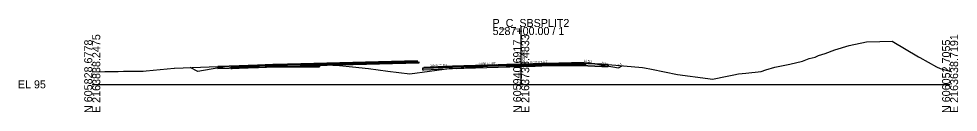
# Model space of a CAD drawing. Extents: x -26 to 1303, y -10 to 12033.
# Drawn here: x -25.7 to 302.8, y 3990.3 to 4022.8 of the extents above; entities that cross this region are included whole.
import ezdxf

# ---------------------------------------------------------------- set-up
doc = ezdxf.new("R2010")
doc.units = 0
for name, color, linetype in [('RD_GPK_XS_Cell', 7, 'Continuous'), ('RD_XS_Base', 7, 'Continuous'), ('RD_XS_ExGround', 7, 'Continuous'), ('RD_XS_ExPaveRet', 7, 'Continuous'), ('RD_XS_Greenside', 7, 'Continuous'), ('RD_XS_Pave', 7, 'Continuous'), ('RD_XS_PaveOvlay_CP', 7, 'Continuous'), ('RD_XS_TieSlope', 7, 'Continuous'), ('RD_XS_TX_Elev_EX', 7, 'Continuous'), ('RD_XS_TX_Elev_PR', 7, 'Continuous'), ('RD_XS_TX_ShdSlope', 7, 'Continuous'), ('RD_XS_TX_Slope', 7, 'Continuous')]:
    doc.layers.add(name, color=color, linetype=linetype)

msp = doc.modelspace()

# ---------------------------------------------------------------- linework, layer by layer
at = {"layer": 'RD_GPK_XS_Cell'}
for p, q in [((150, 4000), (150, 4020)), ((0, 4000), (150, 4000)), ((150, 4000), (300, 4000))]:
    msp.add_line(p, q, dxfattribs=at)
at = {"layer": 'RD_XS_Base'}
for p, q in [((48.51, 4006.03), (48.41, 4006.02)), ((48.41, 4006.02), (48.41, 4005.62)), ((48.41, 4005.62), (48.41, 4005.52)), ((48.41, 4005.52), (48.51, 4005.53)), ((48.91, 4006.04), (48.51, 4006.03)), ((48.51, 4005.53), (48.91, 4005.54)), ((51.32, 4006.14), (48.91, 4006.04)), ((48.91, 4005.54), (51.32, 4005.64)), ((60.91, 4006.52), (51.32, 4006.14)), ((51.32, 4005.64), (60.91, 4006.02)), ((63.58, 4006.59), (60.91, 4006.52)), ((60.91, 4006.02), (63.58, 4006.09)), ((72.91, 4006.84), (63.58, 4006.59)), ((63.58, 4006.09), (72.91, 4006.34)), ((72.91, 4006.84), (114.23, 4007.91)), ((114.23, 4007.41), (72.91, 4006.34)), ((72.91, 4006.34), (72.91, 4006.99)), ((72.91, 4006.99), (72.91, 4006.99)), ((72.91, 4006.99), (72.91, 4006.99)), ((72.91, 4006.99), (72.91, 4006.84)), ((72.91, 4006.84), (72.91, 4006.84)), ((72.91, 4006.34), (72.91, 4006.84)), ((72.91, 4006.84), (72.91, 4006.84)), ((72.91, 4006.84), (72.91, 4006.84)), ((72.91, 4006.34), (72.91, 4006.34)), ((96.91, 4007.46), (96.91, 4007.46)), ((96.91, 4007.46), (96.91, 4007.46)), ((96.91, 4006.96), (96.91, 4006.96)), ((96.91, 4006.96), (96.91, 4006.96)), ((113.73, 4007.9), (113.73, 4007.9)), ((114.23, 4007.91), (114.23, 4007.41)), ((114.23, 4007.88), (114.23, 4007.88)), ((116, 4005.61), (115.5, 4005.59)), ((115.5, 4005.59), (115.5, 4005.59)), ((115.5, 4005.59), (115.5, 4005.09)), ((115.5, 4005.09), (116, 4005.11)), ((126, 4006.01), (116, 4005.61)), ((116, 4005.61), (116, 4005.61)), ((116, 4005.11), (126, 4005.51)), ((116, 4005.11), (116, 4005.11)), ((150, 4006.68), (126, 4006.01)), ((126, 4005.51), (150, 4006.18)), ((126, 4006.01), (126, 4006.01)), ((126, 4005.51), (126, 4005.51)), ((150, 4006.68), (172, 4007.29)), ((150, 4006.18), (150, 4006.84)), ((150, 4006.84), (150, 4006.84)), ((150, 4006.84), (150, 4006.84)), ((150, 4006.84), (150, 4006.68)), ((172.5, 4006.81), (150, 4006.18)), ((150, 4006.68), (150, 4006.68)), ((150, 4006.18), (150, 4006.68)), ((150, 4006.68), (150, 4006.68)), ((150, 4006.68), (150, 4006.68)), ((150, 4006.18), (150, 4006.18)), ((162, 4007.01), (162, 4007.01)), ((162, 4007.01), (162, 4007.01)), ((162, 4006.51), (162, 4006.51)), ((162, 4006.51), (162, 4006.51)), ((172, 4007.29), (172, 4007.29)), ((172.5, 4007.31), (172.5, 4006.81)), ((172.5, 4007.27), (172.5, 4007.27))]:
    msp.add_line(p, q, dxfattribs=at)
at = {"layer": 'RD_XS_ExGround'}
msp.add_lwpolyline([(0, 4004.37), (4.41, 4004.44), (9.06, 4004.53), (10.96, 4004.56), (17.84, 4004.65), (18.81, 4004.66), (28.68, 4005.66), (28.76, 4005.67), (28.78, 4005.67), (43.88, 4006.26), (58.56, 4006.69), (60.53, 4006.75), (62.32, 4006.84), (63.44, 4006.89), (64.65, 4006.89), (79.47, 4006.87), (86.45, 4006.56), (91.02, 4006.15), (96.66, 4005.54), (103.41, 4004.64), (111.03, 4003.62), (124.76, 4005.53), (125.53, 4005.62), (125.59, 4005.62), (127.35, 4005.48), (135.26, 4006.1), (139.62, 4006.41), (144.95, 4006.87), (147.45, 4006.97), (154.9, 4007.13), (157.23, 4007.25), (160.3, 4007.31), (160.68, 4007.27), (163.58, 4007.31), (167.65, 4007.35), (170.9, 4007.34), (178.24, 4007.01), (180.42, 4006.93), (192.44, 4005.82), (193.11, 4005.76), (195.59, 4005.27), (204.64, 4003.49), (215.27, 4002), (216.9, 4001.76), (222.03, 4002.82), (224.37, 4003.3), (225.95, 4003.65), (228.58, 4003.89), (233.88, 4004.46), (235.59, 4005.08), (238.76, 4005.99), (243.96, 4007.02), (248.39, 4008.14), (250.7, 4008.98), (252.84, 4009.51), (254.02, 4010.02), (256.29, 4010.79), (259.74, 4012.01), (264.65, 4013.5), (270.81, 4014.82), (275.43, 4014.95), (279.74, 4015.1), (288.97, 4009.58), (289.16, 4009.47), (289.38, 4009.33), (295.21, 4006.07), (296.5, 4005.51), (298.12, 4005.02), (300, 4004.6)], dxfattribs=at)
at = {"layer": 'RD_XS_ExPaveRet'}
for points in [[(79.47, 4006.87), (79.47, 4006.87), (79.47, 4006.29), (79.47, 4006.12), (79.47, 4006.12), (79.47, 4006.12), (77.26, 4006.12), (64.65, 4006.14), (63.69, 4006.14), (63.44, 4006.14), (63.2, 4006.13), (62.84, 4006.11), (60.62, 4006.01), (60.48, 4006), (58.1, 4005.93), (57.74, 4005.92), (55.8, 4005.86), (43.88, 4005.51), (43.88, 4005.58), (43.88, 4006.26), (55.8, 4006.61), (57.74, 4006.67), (58.1, 4006.68), (60.48, 4006.75), (60.62, 4006.76), (62.84, 4006.86), (63.2, 4006.88), (63.44, 4006.89), (63.69, 4006.89), (64.65, 4006.89), (77.26, 4006.87), (79.47, 4006.87), (79.47, 4006.87)], [(79.47, 4006.87), (77.26, 4006.87), (64.65, 4006.89), (63.69, 4006.89), (63.44, 4006.89), (63.2, 4006.88), (62.84, 4006.86), (60.62, 4006.76), (60.48, 4006.75), (58.1, 4006.68), (57.74, 4006.67), (55.8, 4006.61), (43.88, 4006.26), (43.88, 4005.58), (43.88, 4005.51), (55.8, 4005.86), (57.74, 4005.92), (58.1, 4005.93), (60.48, 4006), (60.62, 4006.01), (62.84, 4006.11), (63.2, 4006.13), (63.44, 4006.14), (63.69, 4006.14), (64.65, 4006.14), (77.26, 4006.12), (79.47, 4006.12), (79.47, 4006.12), (79.47, 4006.29), (79.47, 4006.87)], [(79.47, 4006.87), (79.47, 4006.87)], [(180.42, 4006.93), (180.42, 4006.93), (180.42, 4006.18), (178.24, 4006.26), (178.24, 4006.26), (170.9, 4006.59), (170.9, 4006.59), (170.9, 4006.59), (167.65, 4006.6), (163.58, 4006.56), (163.58, 4006.56), (160.68, 4006.52), (160.68, 4006.52), (160.68, 4006.52), (160.3, 4006.56), (160.3, 4006.56), (157.23, 4006.5), (154.9, 4006.38), (154.9, 4006.38), (147.45, 4006.22), (147.45, 4006.22), (144.95, 4006.12), (144.95, 4006.12), (144.95, 4006.87), (144.95, 4006.87), (144.95, 4006.87), (147.45, 4006.97), (147.45, 4006.97), (154.9, 4007.13), (154.9, 4007.13), (157.23, 4007.25), (160.3, 4007.31), (160.3, 4007.31), (160.68, 4007.27), (160.68, 4007.27), (160.68, 4007.27), (163.58, 4007.31), (163.58, 4007.31), (167.65, 4007.35), (170.9, 4007.34), (170.9, 4007.34), (170.9, 4007.34), (178.24, 4007.01), (178.24, 4007.01), (180.42, 4006.93)], [(178.24, 4007.01), (170.9, 4007.34), (167.65, 4007.35), (163.58, 4007.31), (160.68, 4007.27), (160.3, 4007.31), (157.23, 4007.25), (154.9, 4007.13), (147.45, 4006.97), (144.95, 4006.87), (144.95, 4006.87), (144.95, 4006.12), (144.95, 4006.12), (147.45, 4006.22), (154.9, 4006.38), (157.23, 4006.5), (160.3, 4006.56), (160.68, 4006.52), (163.58, 4006.56), (167.65, 4006.6), (170.9, 4006.59), (178.24, 4006.26), (180.42, 4006.18), (180.42, 4006.93), (178.24, 4007.01)]]:
    msp.add_lwpolyline(points, dxfattribs=at)
at = {"layer": 'RD_XS_Greenside'}
for p, q in [((36.91, 4004.54), (34.23, 4005.88)), ((46.91, 4006.2), (36.91, 4004.54)), ((174, 4007.45), (184, 4005.79)), ((184, 4005.79), (185.37, 4006.47))]:
    msp.add_line(p, q, dxfattribs=at)
at = {"layer": 'RD_XS_Pave'}
for p, q in [((113.73, 4008.21), (72.91, 4007.15)), ((113.73, 4008.06), (113.73, 4008.21)), ((113.73, 4008.21), (113.73, 4008.21)), ((51.32, 4006.46), (48.91, 4006.36)), ((48.91, 4006.36), (48.91, 4006.23)), ((48.91, 4006.2), (51.32, 4006.3)), ((51.32, 4006.3), (48.91, 4006.2)), ((48.91, 4006.23), (48.91, 4006.2)), ((48.91, 4006.2), (48.91, 4006.08)), ((48.91, 4006.04), (51.32, 4006.14)), ((48.91, 4006.08), (48.91, 4006.04)), ((60.91, 4006.84), (51.32, 4006.46)), ((51.32, 4006.3), (60.91, 4006.68)), ((60.91, 4006.68), (51.32, 4006.3)), ((51.32, 4006.14), (60.91, 4006.52)), ((63.58, 4006.91), (60.91, 4006.84)), ((60.91, 4006.68), (63.58, 4006.75)), ((63.58, 4006.75), (60.91, 4006.68)), ((60.91, 4006.52), (63.58, 4006.59)), ((72.91, 4007.15), (63.58, 4006.91)), ((63.58, 4006.75), (72.91, 4006.99)), ((72.91, 4006.99), (63.58, 4006.75)), ((63.58, 4006.59), (72.91, 4006.84)), ((113.73, 4008.06), (72.91, 4006.99)), ((72.91, 4006.99), (113.73, 4008.06)), ((72.91, 4006.84), (113.73, 4007.9)), ((72.91, 4007.15), (72.91, 4007.15)), ((72.91, 4006.99), (72.91, 4006.99)), ((72.91, 4006.99), (72.91, 4006.99)), ((72.91, 4006.99), (72.91, 4006.84)), ((72.91, 4006.99), (72.91, 4006.99)), ((72.91, 4006.84), (72.91, 4006.99)), ((72.91, 4006.99), (72.91, 4006.99)), ((72.91, 4006.99), (72.91, 4006.99)), ((72.91, 4006.84), (72.91, 4006.84)), ((72.91, 4006.84), (72.91, 4006.84)), ((96.91, 4007.78), (96.91, 4007.78)), ((96.91, 4007.78), (96.91, 4007.78)), ((96.91, 4007.62), (96.91, 4007.62)), ((96.91, 4007.62), (96.91, 4007.62)), ((96.91, 4007.62), (96.91, 4007.62)), ((96.91, 4007.62), (96.91, 4007.62)), ((96.91, 4007.46), (96.91, 4007.46)), ((96.91, 4007.46), (96.91, 4007.46)), ((113.73, 4007.9), (113.73, 4008.06)), ((113.73, 4008.06), (113.73, 4008.06)), ((126, 4006.32), (116, 4005.92)), ((116, 4005.77), (126, 4006.17)), ((126, 4006.17), (116, 4005.77)), ((116, 4005.61), (126, 4006.01)), ((116, 4005.92), (116, 4005.92)), ((116, 4005.92), (116, 4005.77)), ((116, 4005.77), (116, 4005.77)), ((116, 4005.77), (116, 4005.61)), ((150, 4007), (126, 4006.32)), ((126, 4006.17), (150, 4006.84)), ((150, 4006.84), (126, 4006.17)), ((126, 4006.01), (150, 4006.68)), ((126, 4006.32), (126, 4006.32)), ((126, 4006.17), (126, 4006.17)), ((126, 4006.17), (126, 4006.17)), ((126, 4006.01), (126, 4006.01)), ((172, 4007.61), (150, 4007)), ((172, 4007.45), (150, 4006.84)), ((150, 4006.84), (172, 4007.45)), ((150, 4006.68), (172.5, 4007.31)), ((150, 4007), (150, 4007)), ((150, 4006.84), (150, 4006.84)), ((150, 4006.84), (150, 4006.84)), ((150, 4006.84), (150, 4006.68)), ((150, 4006.84), (150, 4006.84)), ((150, 4006.68), (150, 4006.84)), ((150, 4006.84), (150, 4006.84)), ((150, 4006.84), (150, 4006.84)), ((150, 4006.68), (150, 4006.68)), ((150, 4006.68), (150, 4006.68)), ((162, 4007.33), (162, 4007.33)), ((162, 4007.33), (162, 4007.33)), ((162, 4007.17), (162, 4007.17)), ((162, 4007.17), (162, 4007.17)), ((162, 4007.17), (162, 4007.17)), ((162, 4007.17), (162, 4007.17)), ((162, 4007.01), (162, 4007.01)), ((162, 4007.01), (162, 4007.01)), ((172, 4007.45), (172, 4007.61)), ((172, 4007.61), (172, 4007.61)), ((172, 4007.29), (172, 4007.45)), ((172, 4007.45), (172, 4007.45))]:
    msp.add_line(p, q, dxfattribs=at)
at = {"layer": 'RD_XS_PaveOvlay_CP'}
for p, q in [((113.73, 4008.21), (72.91, 4007.15)), ((51.32, 4006.46), (48.91, 4006.36)), ((60.91, 4006.84), (51.32, 4006.46)), ((63.58, 4006.91), (60.91, 4006.84)), ((72.91, 4007.15), (63.58, 4006.91)), ((72.91, 4007.15), (72.91, 4007.15)), ((96.91, 4007.78), (96.91, 4007.78)), ((96.91, 4007.78), (96.91, 4007.78)), ((126, 4006.32), (116, 4005.92)), ((150, 4007), (126, 4006.32)), ((126, 4006.32), (126, 4006.32)), ((172, 4007.61), (150, 4007)), ((150, 4007), (150, 4007)), ((162, 4007.33), (162, 4007.33)), ((162, 4007.33), (162, 4007.33))]:
    msp.add_line(p, q, dxfattribs=at)
at = {"layer": 'RD_XS_TieSlope'}
for p, q in [((48.91, 4006.36), (46.91, 4006.2)), ((172, 4007.61), (174, 4007.45))]:
    msp.add_line(p, q, dxfattribs=at)

# ---------------------------------------------------------------- texts
at = {"layer": 'RD_GPK_XS_Cell'}
for s, p in [('P_C_SBSPLIT2', (140, 4020)), ('5287+00.00 / 1', (140, 4017.2)), ('EL 95', (-26, 3998.6))]:
    msp.add_text(s, height=2.8, dxfattribs=at).set_placement(p)
for s, p in [('N 605828.6778', (0, 3990)), ('E 2163838.2475', (2.8, 3990)), ('N 605940.6917', (150, 3990)), ('E 2163738.4833', (152.8, 3990)), ('N 606052.7055', (300, 3990)), ('E 2163638.7191', (302.8, 3990))]:
    msp.add_text(s, height=2.8, rotation=90, dxfattribs=at).set_placement(p)
at = {"layer": 'RD_XS_TX_Elev_EX'}
msp.add_text('102.02', height=0.6, rotation=90, dxfattribs=at).set_placement((149.6, 4007.85))
at = {"layer": 'RD_XS_TX_Elev_PR'}
msp.add_text('102.00', height=1, rotation=90, dxfattribs=at).set_placement((151.32, 4007.49))
at = {"layer": 'RD_XS_TX_ShdSlope'}
msp.add_text('12.5:1', height=0.75, rotation=355.4261, dxfattribs=at).set_placement((171.84, 4007.87))
at = {"layer": 'RD_XS_TX_Slope'}
for s, rotation, p in [('0.030 FT./FT.', 1.7184, (153.16, 4007.29)), ('0.040 FT./FT.', 2.2906, (118.15, 4006.16)), ('0.030 FT./FT.', 1.7184, (135.16, 4006.75)), ('6:1', 350.5358, (178.13, 4007.16)), ('2:1', 26.5651, (183.99, 4006.21))]:
    msp.add_text(s, height=0.75, rotation=rotation, dxfattribs=at).set_placement(p)

doc.saveas('drawing.dxf')
